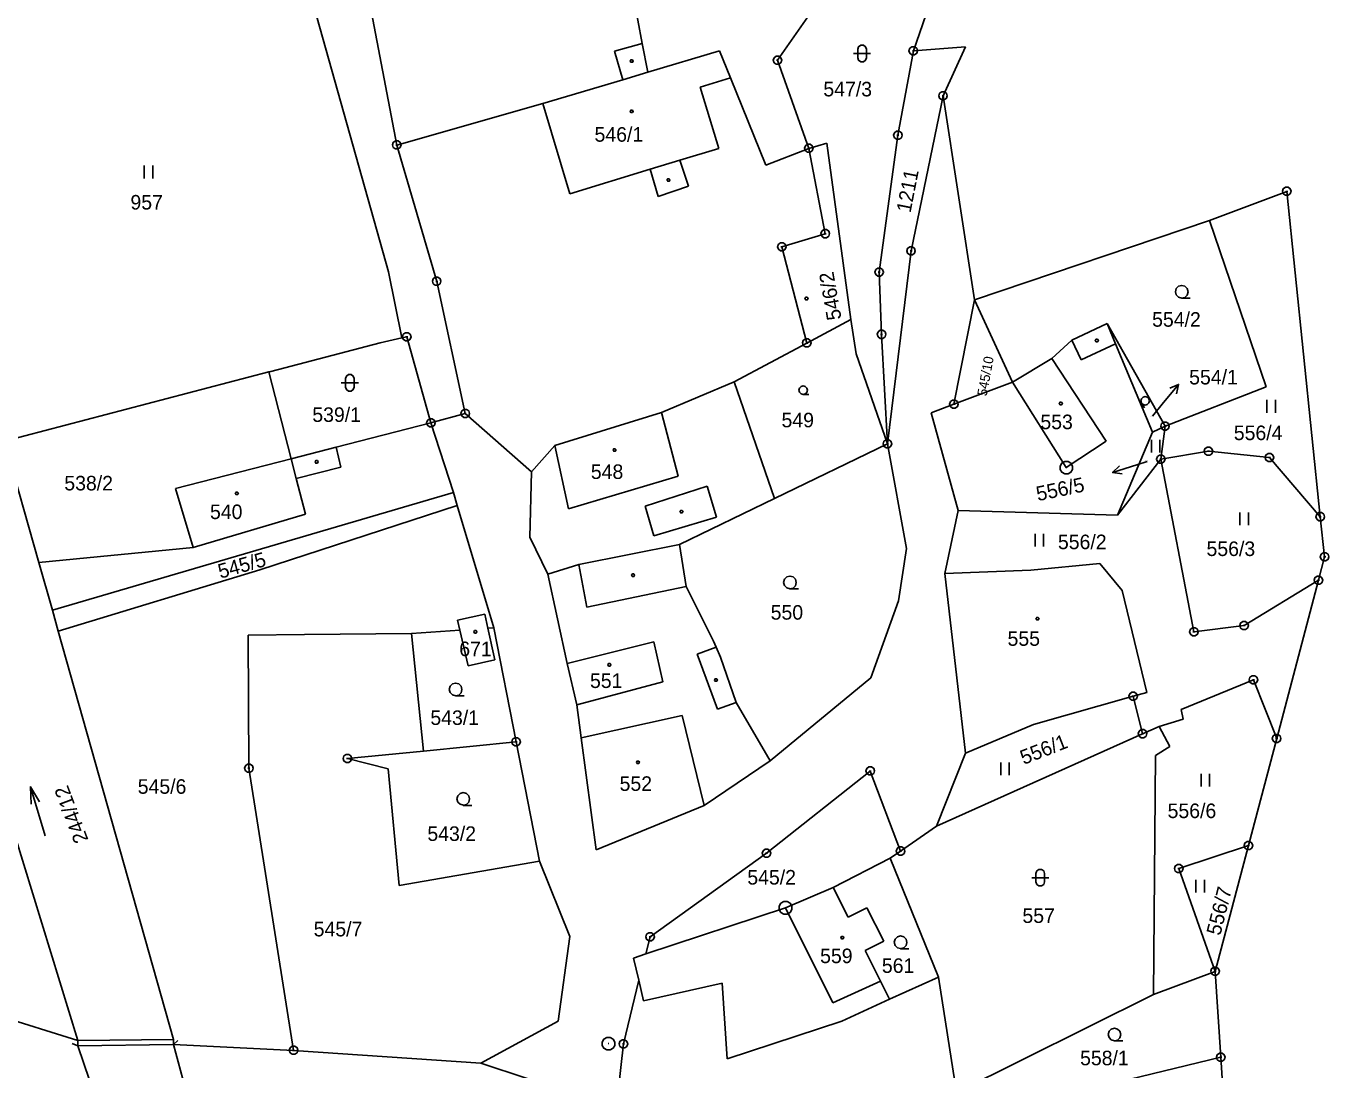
# Model space of a CAD drawing. Extents: x -812394 to -807601, y -1013098 to -1009266.
# Drawn here: x -809003.5 to -808851.2, y -1011690.5 to -1011568.5 of the extents above; entities that cross this region are included whole.
import ezdxf

# ---------------------------------------------------------------- set-up
doc = ezdxf.new("R2010")
doc.units = 0
for name, color, linetype in [('KN_HRANICE', 7, 'Continuous'), ('KN_KULTURY', 7, 'Continuous'), ('KN_MEZNIKY', 7, 'Continuous'), ('KN_PARCELY', 7, 'Continuous'), ('KN_SLUCKY', 7, 'Continuous')]:
    doc.layers.add(name, color=color, linetype=linetype)

# ---------------------------------------------------------------- blocks, each defined once
blk = doc.blocks.new('101')
blk.add_line((-0.05, 0), (0.05, 0))
blk.add_lwpolyline([(0.19, 0.72), (0.53, 0.53), (0.72, 0.19), (0.72, -0.2), (0.53, -0.54), (0.19, -0.73), (-0.2, -0.73), (-0.54, -0.54), (-0.73, -0.2), (-0.73, 0.19), (-0.54, 0.53), (-0.2, 0.72), (0.19, 0.72)])
blk = doc.blocks.new('304')
blk.add_lwpolyline([(0, 0), (-0.38, 0.1), (-0.65, 0.37), (-0.75, 0.74), (-0.65, 1.11), (-0.38, 1.38), (-0.01, 1.48), (0.36, 1.38), (0.63, 1.11), (0.73, 0.73), (0.63, 0.35), (0.36, 0.08), (-0.02, -0.02), (0.98, -0.02)])
blk = doc.blocks.new('306')
for p, q in [((-0.5, 1.5), (-0.5, 0)), ((0.5, 0), (0.5, 1.5))]:
    blk.add_line(p, q)
blk = doc.blocks.new('316')
for points in [[(-0.5, 1.5), (-0.4, 1.79), (-0.15, 1.97), (0.16, 1.97), (0.41, 1.79), (0.51, 1.5), (0.51, 0.5), (0.41, 0.21), (0.16, 0.03), (-0.15, 0.03), (-0.4, 0.21), (-0.5, 0.5), (-0.5, 1.5)], [(-1, 1), (0.27, 1), (1, 1)]]:
    blk.add_lwpolyline(points)
blk = doc.blocks.new('NAHRADNI_SYMBOL')
blk.add_lwpolyline([(0.09, 0.15), (0.18, 0), (0.09, -0.15), (-0.09, -0.15), (-0.18, 0), (-0.09, 0.15), (0.09, 0.15)])
blk = doc.blocks.new('802')
blk.add_line((-3, 0), (3, 0))
blk.add_lwpolyline([(1, 0.5), (3, 0), (1, -0.5)])
blk = doc.blocks.new('10292')
blk.add_line((0, 3), (0, 0))
blk.add_lwpolyline([(-0.5, 2), (0, 3), (0.5, 2)])
blk = doc.blocks.new('402')
blk.add_lwpolyline([(0.09, 0.15), (0.18, 0), (0.09, -0.15), (-0.09, -0.15), (-0.18, 0), (-0.09, 0.15), (0.09, 0.15)])
blk = doc.blocks.new('105')
blk.add_line((-0.12, 0), (0.12, 0))
blk.add_lwpolyline([(0.15, 0.48), (0.4, 0.3), (0.5, 0.01), (0.4, -0.28), (0.15, -0.46), (-0.16, -0.46), (-0.41, -0.28), (-0.51, 0.01), (-0.41, 0.3), (-0.16, 0.48), (0.15, 0.48)])
blk = doc.blocks.new('4201')
blk.add_line((0, 0), (-0.5, -0.5))

msp = doc.modelspace()

# ---------------------------------------------------------------- linework, layer by layer
at = {"layer": 'KN_HRANICE'}
for p, q in [((-808915.66, -1011572.49), (-808880.08, -1011521.57)), ((-808937.15, -1011540.75), (-808931.47, -1011570.52)), ((-808966.39, -1011549.59), (-808960.16, -1011582.4)), ((-808899.78, -1011571.39), (-808894.18, -1011555.33)), ((-808972.29, -1011557.49), (-808961.13, -1011597.23)), ((-808931.47, -1011570.52), (-808934.7, -1011571.43)), ((-808931.47, -1011570.52), (-808930.83, -1011573.88)), ((-808893.7, -1011570.91), (-808899.78, -1011571.39)), ((-808896.31, -1011576.65), (-808893.7, -1011570.91)), ((-808934.7, -1011571.43), (-808933.76, -1011574.76)), ((-808930.83, -1011573.88), (-808922.44, -1011571.37)), ((-808922.44, -1011571.37), (-808921.16, -1011574.54)), ((-808911.99, -1011582.79), (-808915.66, -1011572.49)), ((-808901.58, -1011581.26), (-808899.78, -1011571.39)), ((-808943.1, -1011577.55), (-808933.76, -1011574.76)), ((-808921.16, -1011574.54), (-808917.01, -1011584.77)), ((-808896.31, -1011576.65), (-808900.05, -1011594.78)), ((-808892.65, -1011600.49), (-808896.31, -1011576.65)), ((-808960.16, -1011582.4), (-808943.1, -1011577.55)), ((-808903.77, -1011597.26), (-808901.58, -1011581.26)), ((-808960.16, -1011582.4), (-808955.5, -1011598.34)), ((-808917.01, -1011584.77), (-808911.99, -1011582.79)), ((-808909.89, -1011582.19), (-808911.99, -1011582.79)), ((-808910.08, -1011592.77), (-808911.99, -1011582.79)), ((-808907.08, -1011602.78), (-808909.89, -1011582.19)), ((-808856.13, -1011587.82), (-808865.17, -1011591.23)), ((-808856.13, -1011587.82), (-808852.21, -1011625.86)), ((-808865.17, -1011591.23), (-808892.65, -1011600.49)), ((-808858.54, -1011610.68), (-808865.17, -1011591.23)), ((-808915.15, -1011594.3), (-808910.08, -1011592.77)), ((-808912.24, -1011605.55), (-808915.15, -1011594.3)), ((-808900.05, -1011594.78), (-808902.81, -1011617.34)), ((-808961.13, -1011597.23), (-808959.58, -1011604.96)), ((-808955.5, -1011598.34), (-808952.16, -1011613.79)), ((-808903.49, -1011604.54), (-808903.77, -1011597.26)), ((-808892.65, -1011600.49), (-808895.03, -1011612.7)), ((-808892.65, -1011600.49), (-808888.21, -1011610.12)), ((-808912.24, -1011605.55), (-808907.08, -1011602.78)), ((-808907.08, -1011602.78), (-808906.47, -1011606.8)), ((-808881.24, -1011605.2), (-808877.14, -1011603.27)), ((-808877.14, -1011603.27), (-808870.36, -1011615.27)), ((-808877.14, -1011603.27), (-808876.15, -1011605.63)), ((-808959, -1011604.83), (-808959.58, -1011604.96)), ((-808956.17, -1011614.89), (-808959, -1011604.83)), ((-808902.81, -1011617.34), (-808903.49, -1011604.54)), ((-808962.09, -1011605.51), (-808974.9, -1011608.87)), ((-808959.58, -1011604.96), (-808962.09, -1011605.51)), ((-808920.72, -1011610.1), (-808912.24, -1011605.55)), ((-808883.6, -1011607.34), (-808881.24, -1011605.2)), ((-808876.15, -1011605.63), (-808871.82, -1011615.97)), ((-808906.47, -1011606.8), (-808902.81, -1011617.34)), ((-808888.21, -1011610.12), (-808883.6, -1011607.34)), ((-809006.01, -1011617.04), (-808975.11, -1011608.93)), ((-808974.9, -1011608.87), (-808975.11, -1011608.93)), ((-808972.5, -1011619.08), (-808975.11, -1011608.93)), ((-808929.24, -1011613.67), (-808920.72, -1011610.1)), ((-808920.72, -1011610.1), (-808916.02, -1011623.74)), ((-808888.21, -1011610.12), (-808895.03, -1011612.7)), ((-808870.36, -1011615.27), (-808858.54, -1011610.68)), ((-808952.16, -1011613.79), (-808956.17, -1011614.89)), ((-808944.42, -1011620.59), (-808952.16, -1011613.79)), ((-808941.71, -1011617.53), (-808929.24, -1011613.67)), ((-808895.03, -1011612.7), (-808897.71, -1011613.71)), ((-808897.71, -1011613.71), (-808894.56, -1011625.13)), ((-808967.27, -1011617.74), (-808956.17, -1011614.89)), ((-808956.17, -1011614.89), (-808953.55, -1011623.03)), ((-808871.82, -1011615.97), (-808870.36, -1011615.27)), ((-808870.85, -1011619.12), (-808870.36, -1011615.27)), ((-808871.82, -1011615.97), (-808875.9, -1011625.68)), ((-809002.01, -1011631.2), (-809006.01, -1011617.04)), ((-808972.5, -1011619.08), (-808967.27, -1011617.74)), ((-808941.71, -1011617.53), (-808944.42, -1011620.59)), ((-808916.02, -1011623.74), (-808902.81, -1011617.34)), ((-808902.81, -1011617.34), (-808900.58, -1011629.58)), ((-808870.85, -1011619.12), (-808865.28, -1011618.21)), ((-808865.28, -1011618.21), (-808858.15, -1011618.94)), ((-808986.05, -1011622.56), (-808972.5, -1011619.08)), ((-808875.9, -1011625.68), (-808870.85, -1011619.12)), ((-808866.98, -1011639.31), (-808870.85, -1011619.12)), ((-808858.15, -1011618.94), (-808852.21, -1011625.86)), ((-808944.42, -1011620.59), (-808944.61, -1011628.26)), ((-809000.43, -1011636.79), (-808953.55, -1011623.03)), ((-808983.95, -1011629.44), (-808986.05, -1011622.56)), ((-808953.55, -1011623.03), (-808953.09, -1011624.56)), ((-808953.09, -1011624.56), (-808976.16, -1011632.06)), ((-808948.82, -1011638.83), (-808953.09, -1011624.56)), ((-808927.11, -1011629.12), (-808916.02, -1011623.74)), ((-808896.11, -1011632.48), (-808894.56, -1011625.13)), ((-808894.56, -1011625.13), (-808875.9, -1011625.68)), ((-808851.7, -1011630.55), (-808852.21, -1011625.86)), ((-809015.5, -1011628.37), (-808997.45, -1011687.11)), ((-808944.61, -1011628.26), (-808942.49, -1011632.58)), ((-808927.11, -1011629.12), (-808938.89, -1011631.46)), ((-808926.34, -1011634.03), (-808927.11, -1011629.12)), ((-808983.95, -1011629.44), (-809002.01, -1011631.2)), ((-808900.58, -1011629.58), (-808901.53, -1011635.69)), ((-808852.42, -1011633.29), (-808851.7, -1011630.55)), ((-809000.43, -1011636.79), (-809002.01, -1011631.2)), ((-808976.16, -1011632.06), (-808999.74, -1011639.23)), ((-808938.89, -1011631.46), (-808942.49, -1011632.58)), ((-808886.06, -1011632.1), (-808896.11, -1011632.48)), ((-808877.99, -1011631.31), (-808886.06, -1011632.1)), ((-808875.36, -1011634.48), (-808877.99, -1011631.31)), ((-808942.49, -1011632.58), (-808940.26, -1011643.02)), ((-808896.11, -1011632.48), (-808893.67, -1011653.49)), ((-808852.42, -1011633.29), (-808861.12, -1011638.59)), ((-808852.42, -1011633.29), (-808857.31, -1011651.79)), ((-808926.34, -1011634.03), (-808923.15, -1011640.39)), ((-808872.48, -1011646.42), (-808875.36, -1011634.48)), ((-808999.74, -1011639.23), (-809000.43, -1011636.79)), ((-808901.53, -1011635.69), (-808904.76, -1011644.68)), ((-808949.87, -1011637.24), (-808953.07, -1011637.96)), ((-808952.81, -1011639.12), (-808953.07, -1011637.96)), ((-808949.52, -1011638.88), (-808949.87, -1011637.24)), ((-808986.27, -1011686.97), (-808999.74, -1011639.23)), ((-808970.95, -1011639.63), (-808977.55, -1011639.69)), ((-808977.55, -1011639.69), (-808977.45, -1011655.27)), ((-808958.46, -1011639.52), (-808970.95, -1011639.63)), ((-808952.81, -1011639.12), (-808958.46, -1011639.52)), ((-808958.46, -1011639.52), (-808957.03, -1011653.25)), ((-808952.81, -1011639.12), (-808951.84, -1011643.29)), ((-808948.82, -1011638.83), (-808949.52, -1011638.88)), ((-808949.52, -1011638.88), (-808948.71, -1011642.58)), ((-808948.82, -1011638.83), (-808946.22, -1011652.17)), ((-808861.12, -1011638.59), (-808866.98, -1011639.31)), ((-808923.15, -1011640.39), (-808922.85, -1011641.1)), ((-808922.85, -1011641.1), (-808922.34, -1011642.28)), ((-808951.84, -1011643.29), (-808948.71, -1011642.58)), ((-808922.34, -1011642.28), (-808920.49, -1011647.59)), ((-808939.13, -1011647.83), (-808940.26, -1011643.02)), ((-808904.76, -1011644.68), (-808916.52, -1011654.39)), ((-808860.02, -1011644.93), (-808868.49, -1011648.39)), ((-808857.31, -1011651.79), (-808860.02, -1011644.93)), ((-808885.73, -1011650.13), (-808874.08, -1011646.85)), ((-808874.08, -1011646.85), (-808872.48, -1011646.42)), ((-808872.98, -1011651.23), (-808874.08, -1011646.85)), ((-808938.61, -1011651.69), (-808939.13, -1011647.83)), ((-808920.49, -1011647.59), (-808916.52, -1011654.39)), ((-808868.49, -1011648.39), (-808868.26, -1011649.51)), ((-808926.82, -1011649.1), (-808938.61, -1011651.69)), ((-808924.23, -1011659.63), (-808926.82, -1011649.1)), ((-808893.67, -1011653.49), (-808885.73, -1011650.13)), ((-808871.05, -1011650.4), (-808872.98, -1011651.23)), ((-808868.26, -1011649.51), (-808871.05, -1011650.4)), ((-808869.78, -1011652.71), (-808871.05, -1011650.4)), ((-808936.84, -1011664.82), (-808938.61, -1011651.69)), ((-808872.98, -1011651.23), (-808897.06, -1011662.04)), ((-808857.31, -1011651.79), (-808860.61, -1011664.31)), ((-808965.93, -1011654.13), (-808957.03, -1011653.25)), ((-808957.03, -1011653.25), (-808946.22, -1011652.17)), ((-808946.22, -1011652.17), (-808943.5, -1011666.11)), ((-808893.67, -1011653.49), (-808897.06, -1011662.04)), ((-808871.48, -1011653.76), (-808869.78, -1011652.71)), ((-808965.93, -1011654.13), (-808961.16, -1011655.32)), ((-808916.52, -1011654.39), (-808924.23, -1011659.63)), ((-808871.71, -1011681.7), (-808871.48, -1011653.76)), ((-808977.45, -1011655.27), (-808972.23, -1011688.25)), ((-808961.16, -1011655.32), (-808959.88, -1011668.96)), ((-808904.82, -1011655.59), (-808916.94, -1011665.21)), ((-808901.27, -1011664.95), (-808904.82, -1011655.59)), ((-808924.23, -1011659.63), (-808936.84, -1011664.82)), ((-808897.06, -1011662.04), (-808901.27, -1011664.95)), ((-808916.94, -1011665.21), (-808930.55, -1011674.98)), ((-808901.27, -1011664.95), (-808902.48, -1011665.78)), ((-808860.61, -1011664.31), (-808868.75, -1011667)), ((-808864.5, -1011679.01), (-808860.61, -1011664.31)), ((-808959.88, -1011668.96), (-808943.5, -1011666.11)), ((-808943.5, -1011666.11), (-808939.94, -1011674.92)), ((-808902.48, -1011665.78), (-808909.14, -1011669.19)), ((-808902.48, -1011665.78), (-808896.85, -1011679.68)), ((-808868.75, -1011667), (-808864.5, -1011679.01)), ((-808914.74, -1011671.58), (-808909.14, -1011669.19)), ((-808909.14, -1011669.19), (-808907.39, -1011672.67)), ((-808914.74, -1011671.58), (-808931.05, -1011676.97)), ((-808907.39, -1011672.67), (-808905.21, -1011671.57)), ((-808905.21, -1011671.57), (-808903.24, -1011675.49)), ((-808939.94, -1011674.92), (-808941.31, -1011684.84)), ((-808931.05, -1011676.97), (-808930.55, -1011674.98)), ((-808903.24, -1011675.49), (-808905.42, -1011676.59)), ((-808931.05, -1011676.97), (-808932.49, -1011677.45)), ((-808931.89, -1011680.04), (-808932.49, -1011677.45)), ((-808905.42, -1011676.59), (-808903.63, -1011680.15)), ((-808871.71, -1011681.7), (-808864.5, -1011679.01)), ((-808863.84, -1011689.06), (-808864.5, -1011679.01)), ((-808933.67, -1011687.5), (-808931.89, -1011680.04)), ((-808931.32, -1011682.47), (-808931.89, -1011680.04)), ((-808922.12, -1011680.38), (-808931.32, -1011682.47)), ((-808921.53, -1011689.24), (-808922.12, -1011680.38)), ((-808903.63, -1011680.15), (-808902.57, -1011682.28)), ((-808902.57, -1011682.28), (-808896.85, -1011679.68)), ((-808896.85, -1011679.68), (-808894.75, -1011693.18)), ((-809014.11, -1011681.87), (-808997.45, -1011687.11)), ((-808908.14, -1011684.83), (-808902.57, -1011682.28)), ((-808894.75, -1011693.18), (-808871.71, -1011681.7)), ((-808941.31, -1011684.84), (-808950.35, -1011689.74)), ((-808921.53, -1011689.24), (-808908.14, -1011684.83)), ((-808997.45, -1011687.11), (-808986.27, -1011686.97)), ((-808986.27, -1011686.97), (-808986.26, -1011687.57)), ((-808997.44, -1011687.71), (-808997.45, -1011687.11)), ((-808995.44, -1011693.68), (-808997.44, -1011687.71)), ((-808986.26, -1011687.57), (-808972.23, -1011688.25)), ((-808984.63, -1011693.65), (-808986.26, -1011687.57)), ((-808972.23, -1011688.25), (-808950.35, -1011689.74)), ((-808933.67, -1011687.5), (-808934.28, -1011693.03)), ((-808950.35, -1011689.74), (-808944.94, -1011691.54)), ((-808879.89, -1011692.95), (-808863.84, -1011689.06)), ((-808861.85, -1011719.28), (-808863.84, -1011689.06))]:
    msp.add_line(p, q, dxfattribs=at)
at = {"layer": 'KN_PARCELY'}
for p, q in [((-808871.82, -1011614.11), (-808870.68, -1011612.71)), ((-808872.46, -1011619.39), (-808873.64, -1011619.77))]:
    msp.add_line(p, q, dxfattribs=at)
at = {"layer": 'KN_SLUCKY'}
for p, q in [((-808933.76, -1011574.76), (-808930.83, -1011573.88)), ((-808924.71, -1011575.62), (-808921.16, -1011574.54)), ((-808922.53, -1011582.8), (-808924.71, -1011575.62)), ((-808943.1, -1011577.55), (-808939.94, -1011588.09)), ((-808927.09, -1011584.18), (-808922.53, -1011582.8)), ((-808930.53, -1011585.23), (-808927.09, -1011584.18)), ((-808926.07, -1011587.22), (-808927.09, -1011584.18)), ((-808939.94, -1011588.09), (-808930.53, -1011585.23)), ((-808930.53, -1011585.23), (-808929.61, -1011588.4)), ((-808929.61, -1011588.4), (-808926.07, -1011587.22)), ((-808881.24, -1011605.2), (-808880.15, -1011607.51)), ((-808880.15, -1011607.51), (-808876.15, -1011605.63)), ((-808883.6, -1011607.34), (-808877.26, -1011617.01)), ((-808881.92, -1011620.12), (-808888.21, -1011610.12)), ((-808929.24, -1011613.67), (-808927.28, -1011621.11)), ((-808877.26, -1011617.01), (-808881.92, -1011620.12)), ((-808966.69, -1011620.05), (-808967.27, -1011617.74)), ((-808940.08, -1011624.95), (-808941.71, -1011617.53)), ((-808971.91, -1011621.37), (-808972.5, -1011619.08)), ((-808971.91, -1011621.37), (-808966.69, -1011620.05)), ((-808970.84, -1011625.57), (-808971.91, -1011621.37)), ((-808927.28, -1011621.11), (-808940.08, -1011624.95)), ((-808931.14, -1011624.64), (-808923.87, -1011622.27)), ((-808923.87, -1011622.27), (-808922.78, -1011625.91)), ((-808970.84, -1011625.57), (-808983.95, -1011629.44)), ((-808930.11, -1011628.1), (-808931.14, -1011624.64)), ((-808922.78, -1011625.91), (-808930.11, -1011628.1)), ((-808938.89, -1011631.46), (-808937.94, -1011636.42)), ((-808937.94, -1011636.42), (-808926.34, -1011634.03)), ((-808940.26, -1011643.02), (-808930.1, -1011640.49)), ((-808930.1, -1011640.49), (-808929.06, -1011645.16)), ((-808925.04, -1011641.91), (-808922.85, -1011641.1)), ((-808922.67, -1011648.35), (-808925.04, -1011641.91)), ((-808929.06, -1011645.16), (-808939.13, -1011647.83)), ((-808920.49, -1011647.59), (-808922.67, -1011648.35)), ((-808909.19, -1011682.69), (-808914.74, -1011671.58)), ((-808903.63, -1011680.15), (-808909.19, -1011682.69)), ((-808997.44, -1011687.71), (-808986.26, -1011687.57))]:
    msp.add_line(p, q, dxfattribs=at)

# ---------------------------------------------------------------- block references
at = {"layer": 'KN_KULTURY'}
for name, p in [('316', (-808905.78, -1011572.69)), ('402', (-808932.7, -1011572.58)), ('402', (-808932.71, -1011578.46)), ('306', (-808989.19, -1011586.3)), ('402', (-808928.41, -1011586.49)), ('NAHRADNI_SYMBOL', (-808912.27, -1011600.35)), ('304', (-808868.4, -1011600.29)), ('402', (-808878.33, -1011605.25)), ('316', (-808965.66, -1011611.21)), ('306', (-808857.95, -1011613.7)), ('402', (-808882.54, -1011612.61)), ('306', (-808871.45, -1011618.36)), ('402', (-808934.71, -1011618.05)), ('402', (-808969.54, -1011619.45)), ('402', (-808978.86, -1011623.12)), ('402', (-808926.88, -1011625.27)), ('306', (-808861.1, -1011626.85)), ('306', (-808885.05, -1011629.35)), ('402', (-808932.54, -1011632.7)), ('304', (-808914.2, -1011634.28)), ('NAHRADNI_SYMBOL', (-808885.27, -1011637.77)), ('402', (-808950.98, -1011639.31)), ('402', (-808935.32, -1011643.16)), ('304', (-808953.28, -1011646.78)), ('402', (-808922.86, -1011644.95)), ('NAHRADNI_SYMBOL', (-808931.98, -1011654.57)), ('306', (-808889.07, -1011656.09)), ('306', (-808865.65, -1011657.4)), ('304', (-808952.38, -1011659.58)), ('316', (-808884.95, -1011669.06)), ('306', (-808866.25, -1011669.81)), ('304', (-808901.27, -1011676.35)), ('402', (-808908.09, -1011675.07)), ('304', (-808876.26, -1011687.13))]:
    msp.add_blockref(name, p, dxfattribs=at)
at = {"layer": 'KN_KULTURY', "xscale": 0.67, "yscale": 0.67}
msp.add_blockref('304', (-808912.65, -1011611.56), dxfattribs=at)
at = {"layer": 'KN_KULTURY', "xscale": 0.67, "yscale": 0.6699999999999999, "rotation": -59.598228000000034}
msp.add_blockref('304', (-808873.1, -1011612.57), dxfattribs=at)
at = {"layer": 'KN_KULTURY', "rotation": 106.913925}
msp.add_blockref('802', (-809002.13, -1011660.29), dxfattribs=at)
at = {"layer": 'KN_MEZNIKY'}
for name, p in [('105', (-808899.78, -1011571.39)), ('105', (-808915.66, -1011572.49)), ('105', (-808896.31, -1011576.65)), ('105', (-808960.16, -1011582.4)), ('105', (-808901.58, -1011581.26)), ('105', (-808911.99, -1011582.79)), ('105', (-808856.13, -1011587.82)), ('105', (-808910.08, -1011592.77)), ('105', (-808915.15, -1011594.3)), ('105', (-808900.05, -1011594.78)), ('105', (-808903.77, -1011597.26)), ('105', (-808955.5, -1011598.34)), ('105', (-808959, -1011604.83)), ('105', (-808903.49, -1011604.54)), ('105', (-808912.24, -1011605.55)), ('105', (-808895.03, -1011612.7)), ('105', (-808952.16, -1011613.79)), ('105', (-808956.17, -1011614.89)), ('105', (-808870.36, -1011615.27)), ('105', (-808902.81, -1011617.34)), ('105', (-808865.28, -1011618.21)), ('105', (-808858.15, -1011618.94)), ('101', (-808881.89, -1011620.12)), ('105', (-808870.85, -1011619.12)), ('105', (-808852.21, -1011625.86)), ('105', (-808851.7, -1011630.55)), ('105', (-808852.42, -1011633.29)), ('105', (-808861.12, -1011638.59)), ('105', (-808866.98, -1011639.31)), ('105', (-808860.02, -1011644.93)), ('105', (-808874.08, -1011646.85)), ('105', (-808946.22, -1011652.17)), ('105', (-808872.98, -1011651.23)), ('105', (-808857.31, -1011651.79)), ('105', (-808977.45, -1011655.27)), ('105', (-808965.93, -1011654.13)), ('105', (-808904.82, -1011655.59)), ('105', (-808860.61, -1011664.31)), ('105', (-808916.94, -1011665.21)), ('105', (-808901.27, -1011664.95)), ('105', (-808868.75, -1011667)), ('101', (-808914.72, -1011671.58)), ('105', (-808930.55, -1011674.98)), ('105', (-808864.5, -1011679.01)), ('101', (-808935.41, -1011687.46)), ('105', (-808933.67, -1011687.5)), ('105', (-808972.23, -1011688.25)), ('105', (-808863.84, -1011689.06))]:
    msp.add_blockref(name, p, dxfattribs=at)
at = {"layer": 'KN_PARCELY'}
for p, rotation in [((-808870.68, -1011612.71), -39.25822599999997), ((-808873.64, -1011619.77), 107.830657)]:
    msp.add_blockref('10292', p, dxfattribs=dict(at, rotation=rotation))
at = {"layer": 'KN_SLUCKY'}
for p, rotation in [((-808986.26, -1011687.57), 179.33579), ((-808997.44, -1011687.71), -65.90076400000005)]:
    msp.add_blockref('4201', p, dxfattribs=dict(at, rotation=rotation))

# ---------------------------------------------------------------- texts
at = {"layer": 'KN_PARCELY'}
for s, height, p in [('547/3', 1.7, (-808910.3, -1011576.71)), ('546/1', 1.7, (-808937.05, -1011582.01)), ('957', 1.7, (-808991.3, -1011589.94)), ('554/2', 1.7, (-808871.87, -1011603.64)), ('554/1', 1.7, (-808867.54, -1011610.39)), ('539/1', 1.7, (-808970.04, -1011614.77)), ('549', 1.7, (-808915.19, -1011615.4)), ('553', 1.7, (-808884.93, -1011615.62)), ('554/1', 0.1, (-808872.05, -1011614.11)), ('556/4', 1.7, (-808862.32, -1011616.9)), ('548', 1.7, (-808937.48, -1011621.44)), ('556/5', 0.1, (-808872.7, -1011619.39)), ('538/2', 1.7, (-808999.03, -1011622.78)), ('540', 1.7, (-808982, -1011626.13)), ('556/2', 1.7, (-808882.88, -1011629.65)), ('556/3', 1.7, (-808865.51, -1011630.45)), ('550', 1.7, (-808916.46, -1011637.89)), ('555', 1.7, (-808888.77, -1011640.95)), ('671', 1.7, (-808952.86, -1011642.16)), ('551', 1.7, (-808937.58, -1011645.88)), ('543/1', 1.7, (-808956.24, -1011650.2)), ('545/6', 1.7, (-808990.45, -1011658.25)), ('552', 1.7, (-808934.12, -1011657.91)), ('556/6', 1.7, (-808870.06, -1011661.09)), ('543/2', 1.7, (-808956.59, -1011663.76)), ('545/2', 1.7, (-808919.19, -1011668.86)), ('557', 1.7, (-808887.03, -1011673.35)), ('545/7', 1.7, (-808969.88, -1011674.92)), ('559', 1.7, (-808910.68, -1011678.05)), ('561', 1.7, (-808903.46, -1011679.19)), ('558/1', 1.7, (-808880.29, -1011689.99))]:
    msp.add_text(s, height=height, dxfattribs=at).set_placement(p)
for s, height, rotation, p in [('1211', 1.7, 78.954, (-808900.11, -1011590.39)), ('546/2', 1.7, 99.809, (-808908.17, -1011602.72)), ('545/10', 1.14, 79.698, (-808891.21, -1011611.81)), ('556/5', 1.7, 11.746, (-808885.23, -1011624.04)), ('545/5', 1.7, 15.584, (-808980.79, -1011633.11)), ('556/1', 1.7, 21.314, (-808886.89, -1011654.88)), ('244/12', 1.7, 110.695, (-808996.19, -1011663.64)), ('556/7', 1.7, 75.974, (-808863.9, -1011674.9))]:
    msp.add_text(s, height=height, rotation=rotation, dxfattribs=at).set_placement(p)

doc.saveas('drawing.dxf')
